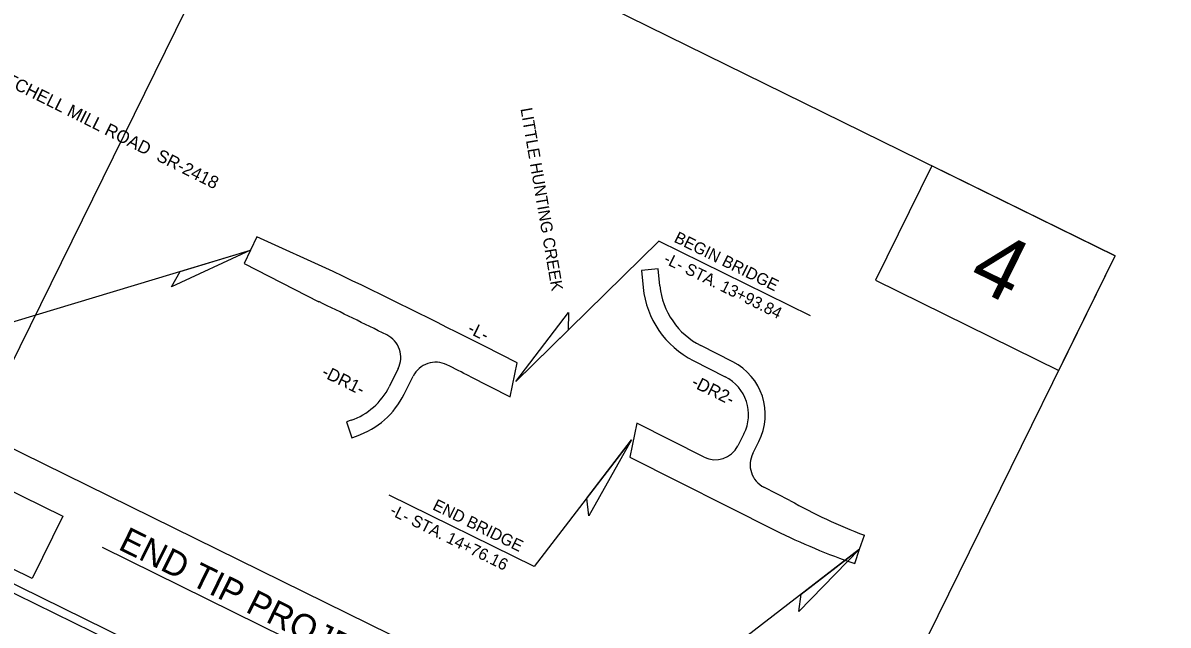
# Model space of a CAD drawing. Extents: x 1428128 to 1430390, y 857947 to 859822.
# Drawn here: x 1429306 to 1429989, y 858523 to 858882 of the extents above; entities that cross this region are included whole.
import ezdxf

# ---------------------------------------------------------------- set-up
doc = ezdxf.new("R2010")
doc.units = 0
for name, color, linetype in [('Old_Level_1', 7, 'Continuous'), ('Sheet Data Field CELL', 7, 'Continuous'), ('Sheet Title CELL', 7, 'Continuous')]:
    doc.layers.add(name, color=color, linetype=linetype)

msp = doc.modelspace()

# ---------------------------------------------------------------- linework, layer by layer
at = {"layer": 'Old_Level_1'}
for p, q in [((1429599.58, 858667.88), (1429684.92, 858751.69)), ((1429775.52, 858707.11), (1429684.92, 858751.69)), ((1429246.24, 858687.55), (1429441.35, 858746.29)), ((1429668.68, 858633.04), (1429610.6, 858557.51)), ((1429610.6, 858557.51), (1429524.13, 858600.06)), ((1429629.26, 858432.82), (1429353.02, 858568.75)), ((1429804.75, 858567.76), (1429629.26, 858432.82))]:
    msp.add_line(p, q, dxfattribs=at)
for points in [[(1429441.35, 858746.29), (1429394.18, 858724.4), (1429399.29, 858733.63)], [(1429599.58, 858667.88), (1429631.15, 858709.2), (1429630.92, 858698.66)], [(1429668.68, 858633.04), (1429643.13, 858587.74), (1429641.9, 858598.22)], [(1429804.75, 858567.76), (1429768.43, 858530.54), (1429769.92, 858540.98)]]:
    msp.add_lwpolyline(points, close=True, dxfattribs=at)
at = {"layer": 'Sheet Data Field CELL'}
for p, q in [((1429452.45, 858991.29), (1429957.18, 858742.93)), ((1429490.74, 858733.62), (1429445.19, 858754.28)), ((1429437.55, 858738.38), (1429482.07, 858715.59)), ((1429684.53, 858735.14), (1429674.59, 858734.13)), ((1429685.56, 858725), (1429684.53, 858735.14)), ((1429674.59, 858734.13), (1429675.61, 858723.99)), ((1429600.47, 858679.14), (1429581.03, 858688.96)), ((1429729.06, 858679.71), (1429709.98, 858689.38)), ((1429529.44, 858675.65), (1429524.09, 858664.84)), ((1429596.24, 858658.87), (1429600.47, 858679.14)), ((1429705.46, 858680.46), (1429724.53, 858670.79)), ((1429533.05, 858660.4), (1429538.37, 858671.14)), ((1429572.01, 858671.1), (1429596.24, 858658.87)), ((1429501.36, 858644.81), (1429498.54, 858643.83)), ((1429498.54, 858643.83), (1429501.81, 858634.38)), ((1429671.88, 858643.07), (1429667.65, 858622.8)), ((1429711.94, 858622.83), (1429671.88, 858643.07)), ((1429501.81, 858634.38), (1429504.64, 858635.37)), ((1429735.71, 858636.61), (1429732.08, 858629.44)), ((1429741.03, 858624.97), (1429744.63, 858632.08)), ((1429667.65, 858622.8), (1429754.51, 858578.92)), ((1429763.18, 858596.95), (1429747.64, 858604.8))]:
    msp.add_line(p, q, dxfattribs=at)
for points in [[(1429452.45, 858991.29), (1429278.61, 858637.99), (1429783.32, 858389.64), (1429957.17, 858742.94)], [(1429445.19, 858754.28), (1429441.35, 858746.29), (1429437.55, 858738.38)], [(1429522.64, 858695.76), (1429522.64, 858695.76)], [(1429558.54, 858677.89), (1429558.54, 858677.89)], [(1429801.88, 858559.19), (1429804.75, 858567.76), (1429807.56, 858576.16)]]:
    msp.add_lwpolyline(points, dxfattribs=at)
msp.add_lwpolyline([(1429957.18, 858742.93), (1429847.75, 858796.78), (1429814.12, 858728.44), (1429923.55, 858674.59)], close=True, dxfattribs=at)
for centre, radius, start, end in [((1426871.37, 853324.46), 6010, 63.201249, 64.161606), ((1429730.33, 858729.51), 55, 185.76159, 243.11111), ((1429730.33, 858729.51), 45, 185.76159, 243.11111), ((1426871.37, 853324.46), 5990, 63.729104, 64.161062), ((1429516, 858682.31), 15, 333.63875, 63.7291), ((1429551.81, 858664.48), 15, 63.34566, 153.63875), ((1426871.37, 853324.46), 5990, 63.201249, 63.345533), ((1429713.03, 858648.11), 35.43, 333.11111, 63.11111), ((1429713.03, 858648.11), 25.43, 333.11111, 63.11111), ((1429488.25, 858682.6), 40, 289.14043, 333.63875), ((1429488.25, 858682.6), 50, 289.14043, 333.63875), ((1429718.7, 858636.22), 15, 243.20125, 333.11111), ((1429754.4, 858618.19), 15, 153.11111, 243.20125), ((1429917.18, 858867.88), 311.64, 240.386, 249.40575), ((1429942.95, 858964.62), 429.27, 243.96138, 250.81469)]:
    msp.add_arc(centre, radius, start, end, dxfattribs=at)
at = {"layer": 'Sheet Title CELL'}
for p, q in [((1428714.68, 858835.22), (1429988.78, 858208.28)), ((1429017.53, 858680.61), (1429358.49, 858512.84))]:
    msp.add_line(p, q, dxfattribs=at)
msp.add_lwpolyline([(1428741, 858877.16), (1429329.45, 858587.61), (1429311.12, 858550.35), (1428722.66, 858839.9)], close=True, dxfattribs=at)

# ---------------------------------------------------------------- texts
at = {"layer": 'Old_Level_1'}
for s, height, rotation, p in [('MITCHELL MILL ROAD  SR-2418', 7.5, 333.36553, (1429284.43, 858850.49)), ('LITTLE HUNTING CREEK', 7, 279.69033, (1429602.4, 858830.77)), ('BEGIN BRIDGE', 7, 333.80011, (1429693.52, 858751.49)), ('-L- STA. 13+93.84 ', 7, 333.80011, (1429687.34, 858738.93)), ('-L-', 7.5, 333.80011, (1429570.33, 858697.23)), ('-DR1-', 7.5, 333.80011, (1429483.24, 858671.24)), ('-DR2-', 7.5, 333.80011, (1429703.82, 858665.25)), ('-L- STA. 14+76.16', 7, 333.80011, (1429523.92, 858588.74)), ('END BRIDGE', 7, 333.80011, (1429549.47, 858591.77))]:
    msp.add_text(s, height=height, rotation=rotation, dxfattribs=at).set_placement(p)
at = {"layer": 'Sheet Data Field CELL'}
for s, height, p in [('4', 37.5, (1429868.03, 858726.19)), ('END TIP PROJECT B-4846', 15, (1429361.82, 858568.06))]:
    msp.add_text(s, height=height, rotation=333.80011, dxfattribs=at).set_placement(p)

doc.saveas('drawing.dxf')
